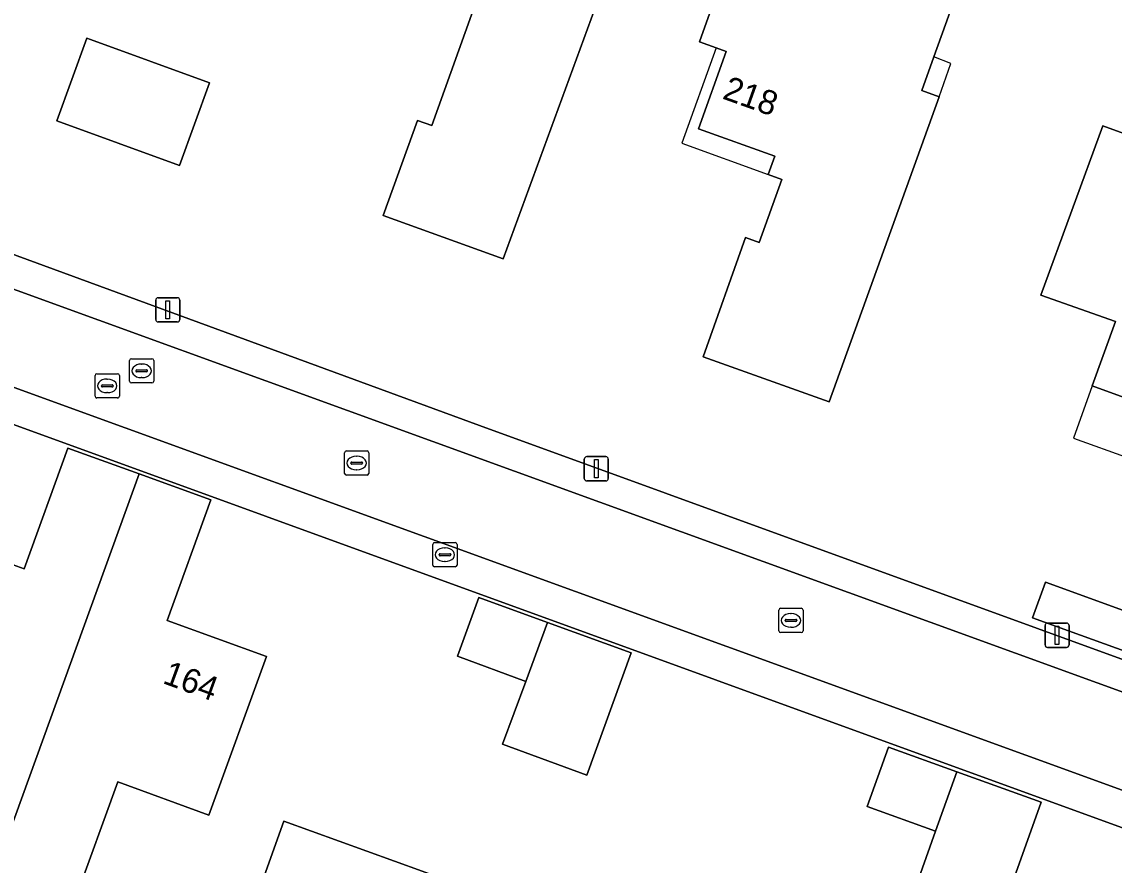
# Model space of a CAD drawing. Extents: x 155275 to 156265, y 382654 to 383635.
# Drawn here: x 155842.67 to 155887.75, y 382975.69 to 383010.47 of the extents above; entities that cross this region are included whole.
import ezdxf

# ---------------------------------------------------------------- set-up
doc = ezdxf.new("R2010")
doc.units = 0
for name, color, linetype in [('IMGEO_Brandkraan', 7, 'Continuous'), ('IMGEO_Erf', 7, 'Continuous'), ('IMGEO_Kolk', 7, 'Continuous'), ('IMGEO_Lichtmast', 7, 'Continuous'), ('IMGEO_Pand', 7, 'Continuous'), ('IMGEO_Pand_nummerreeks', 7, 'Continuous'), ('IMGEO_Pand_overbouw', 7, 'Continuous'), ('IMGEO_Rijbaan_lokaal_open', 7, 'Continuous'), ('IMGEO_Rioolput', 7, 'Continuous'), ('IMGEO_Voetpad_open', 7, 'Continuous')]:
    doc.layers.add(name, color=color, linetype=linetype)

msp = doc.modelspace()

# ---------------------------------------------------------------- linework, layer by layer
at = {"layer": 'IMGEO_Brandkraan'}
for p, q in [((155859.627, 382988.068), (155859.627, 382988.92)), ((155859.702, 382988.994), (155860.554, 382988.994)), ((155860.115, 382988.774), (155860.14, 382988.774)), ((155860.628, 382988.92), (155860.628, 382988.068)), ((155859.886, 382988.488), (155859.886, 382988.5)), ((155860.324, 382988.451), (155859.926, 382988.451)), ((155859.929, 382988.537), (155860.327, 382988.537)), ((155860.138, 382988.214), (155860.113, 382988.214)), ((155860.37, 382988.5), (155860.37, 382988.488)), ((155860.554, 382987.994), (155859.702, 382987.994))]:
    msp.add_line(p, q, dxfattribs=at)
for points in [[(155859.627, 382988.068), (155859.627, 382988.92)], [(155859.702, 382988.994), (155860.554, 382988.994)], [(155860.628, 382988.92), (155860.628, 382988.068)], [(155860.554, 382987.994), (155859.702, 382987.994)]]:
    msp.add_lwpolyline(points, dxfattribs=at)
for centre, radius, start, end in [((155859.704, 382988.918), 0.0765, 91.552, 178.448), ((155859.704, 382988.918), 0.0765, 91.552, 178.448), ((155860.552, 382988.918), 0.0765, 1.552, 88.448), ((155860.552, 382988.918), 0.0765, 1.552, 88.448), ((155859.926, 382988.497), 0.0403, 85.8775, 175.7526), ((155859.923, 382988.487), 0.0366, 178.938, 274.7102), ((155860.327, 382988.494), 0.043, 264.8664, 352.4533), ((155860.331, 382988.499), 0.0386, 1.7309, 96.639), ((155859.704, 382988.07), 0.0765, 181.552, 268.448), ((155859.704, 382988.07), 0.0765, 181.552, 268.448), ((155860.552, 382988.07), 0.0765, 271.552, 358.448), ((155860.552, 382988.07), 0.0765, 271.552, 358.448)]:
    msp.add_arc(centre, radius, start, end, dxfattribs=at)
for centre, major_axis, ratio, start_param, end_param in [((155860.114, 382988.494), (-0.387, 0.002), 0.722429, 4.712389, 7.853982), ((155860.139, 382988.494), (-0.39, 0.002), 0.717154, 1.570796, 4.712389)]:
    msp.add_ellipse(centre, major_axis=major_axis, ratio=ratio, start_param=start_param, end_param=end_param, dxfattribs=at)
at = {"layer": 'IMGEO_Erf'}
for points in [[(155874.118, 383022.07), (155815.634, 383043.488), (155805.118, 383014.525), (155861.561, 382993.83), (155892.261, 382982.665), (155902.833, 383011.607)], [(155861.487, 383011.501), (155860.894, 383011.717), (155856.676, 383013.255), (155859.79, 383021.938), (155866.043, 383019.627), (155865.514, 383018.043), (155867.383, 383017.419), (155866.395, 383014.46), (155867.37, 383014.134), (155866.468, 383011.433), (155862.536, 383000.703), (155857.581, 383002.491), (155858.991, 383006.402), (155859.584, 383006.197)], [(155871.739, 383009.255), (155871.329, 383009.401), (155870.641, 383009.646), (155873.267, 383017.02), (155882.058, 383013.885), (155880.313, 383009.036), (155879.812, 383007.643), (155880.526, 383007.379), (155875.99, 382994.801), (155870.783, 382996.663), (155872.541, 383001.578), (155873.106, 383001.376), (155874.035, 383003.975), (155873.47, 383004.177), (155873.743, 383004.94), (155870.598, 383006.064)], [(155850.407, 383007.954), (155849.167, 383004.553), (155844.112, 383006.396), (155845.352, 383009.797), (155845.493, 383009.746)], [(155887.289, 383006.185), (155889.215, 383005.483), (155889.922, 383007.421), (155891.006, 383007.026), (155891.151, 383006.973), (155892.124, 383009.662), (155898.589, 383007.324), (155897.186, 383003.474), (155897.411, 383003.391), (155897.936, 383003.196), (155896.655, 382999.777), (155896.075, 382999.984), (155895.342, 382998.021), (155897.361, 382997.282), (155892.159, 382983.084), (155884.378, 382985.893), (155884.916, 382987.368), (155888.598, 382986.024), (155890.664, 382991.645), (155891.448, 382993.777), (155886.85, 382995.454), (155887.812, 382998.113), (155884.727, 382999.207)], [(155815.563, 383003.587), (155803.373, 383007.958), (155803.344, 383007.878), (155814.627, 383003.794), (155812.383, 382997.713), (155807.505, 382999.513), (155802.482, 382985.7), (155800.143, 382986.554), (155799.514, 382984.832), (155798.857, 382983.032), (155794.84, 382984.507), (155794.244, 382982.888), (155817.258, 382974.414), (155845.91, 382964.137), (155880.792, 382951.626), (155889.819, 382976.447), (155889.87, 382976.588)], [(155840.019, 382981.509), (155837.391, 382982.474), (155838.538, 382985.6), (155837.416, 382986.01), (155838.657, 382989.39), (155842.761, 382987.916), (155844.568, 382992.891), (155847.501, 382991.829), (155850.461, 382990.758), (155848.665, 382985.778), (155852.768, 382984.295), (155850.381, 382977.751), (155846.624, 382979.121), (155844.881, 382974.314), (155848.641, 382972.949), (155846.046, 382965.802), (155838.99, 382968.361), (155831.934, 382970.92), (155832.069, 382971.267), (155834.531, 382978.054), (155838.252, 382976.693)], [(155863.462, 382983.266), (155860.642, 382984.304), (155861.532, 382986.731), (155864.36, 382985.703), (155867.817, 382984.447), (155865.992, 382979.402), (155862.509, 382980.678)], [(155878.437, 382980.551), (155881.26, 382979.539), (155884.744, 382978.29), (155882.935, 382973.245), (155879.452, 382974.493), (155880.383, 382977.091), (155877.559, 382978.104)], [(155853.474, 382977.5), (155859.184, 382975.435), (155860.453, 382974.972), (155867.583, 382972.373), (155865.394, 382966.345), (155864.103, 382966.792), (155861.667, 382960.114), (155855.679, 382962.284), (155856.389, 382964.171), (155850.842, 382966.173), (155852.91, 382971.892), (155851.641, 382972.351)]]:
    msp.add_lwpolyline(points, close=True, dxfattribs=at)
at = {"layer": 'IMGEO_Kolk'}
for p, q in [((155855.986, 382991.849), (155855.986, 382992.701)), ((155856.061, 382992.775), (155856.913, 382992.775)), ((155856.987, 382992.701), (155856.987, 382991.849)), ((155856.245, 382992.269), (155856.245, 382992.281)), ((155856.683, 382992.232), (155856.285, 382992.232)), ((155856.288, 382992.318), (155856.686, 382992.318)), ((155856.474, 382992.555), (155856.499, 382992.555)), ((155856.729, 382992.281), (155856.729, 382992.269)), ((155856.497, 382991.995), (155856.472, 382991.995)), ((155856.913, 382991.775), (155856.061, 382991.775)), ((155873.911, 382985.357), (155873.911, 382986.209)), ((155873.986, 382986.283), (155874.838, 382986.283)), ((155874.399, 382986.063), (155874.424, 382986.063)), ((155874.912, 382986.209), (155874.912, 382985.357)), ((155874.17, 382985.777), (155874.17, 382985.789)), ((155874.608, 382985.74), (155874.21, 382985.74)), ((155874.213, 382985.826), (155874.611, 382985.826)), ((155874.422, 382985.503), (155874.397, 382985.503)), ((155874.654, 382985.789), (155874.654, 382985.777)), ((155874.838, 382985.283), (155873.986, 382985.283))]:
    msp.add_line(p, q, dxfattribs=at)
for points in [[(155855.986, 382991.849), (155855.986, 382992.701)], [(155856.061, 382992.775), (155856.913, 382992.775)], [(155856.987, 382992.701), (155856.987, 382991.849)], [(155856.913, 382991.775), (155856.061, 382991.775)], [(155873.911, 382985.357), (155873.911, 382986.209)], [(155873.986, 382986.283), (155874.838, 382986.283)], [(155874.912, 382986.209), (155874.912, 382985.357)], [(155874.838, 382985.283), (155873.986, 382985.283)]]:
    msp.add_lwpolyline(points, dxfattribs=at)
for centre, radius, start, end in [((155856.063, 382992.699), 0.0765, 91.552, 178.448), ((155856.063, 382992.699), 0.0765, 91.552, 178.448), ((155856.911, 382992.699), 0.0765, 1.552, 88.448), ((155856.911, 382992.699), 0.0765, 1.552, 88.448), ((155856.285, 382992.278), 0.0403, 85.8775, 175.7526), ((155856.282, 382992.268), 0.0366, 178.938, 274.7102), ((155856.686, 382992.275), 0.043, 264.8664, 352.4533), ((155856.69, 382992.28), 0.0386, 1.7309, 96.639), ((155856.063, 382991.851), 0.0765, 181.552, 268.448), ((155856.063, 382991.851), 0.0765, 181.552, 268.448), ((155856.911, 382991.851), 0.0765, 271.552, 358.448), ((155856.911, 382991.851), 0.0765, 271.552, 358.448), ((155873.988, 382986.207), 0.0765, 91.552, 178.448), ((155873.988, 382986.207), 0.0765, 91.552, 178.448), ((155874.836, 382986.207), 0.0765, 1.552, 88.448), ((155874.836, 382986.207), 0.0765, 1.552, 88.448), ((155874.21, 382985.786), 0.0403, 85.8775, 175.7526), ((155874.207, 382985.776), 0.0366, 178.938, 274.7102), ((155874.611, 382985.783), 0.043, 264.8664, 352.4533), ((155874.615, 382985.788), 0.0386, 1.7309, 96.639), ((155873.988, 382985.359), 0.0765, 181.552, 268.448), ((155873.988, 382985.359), 0.0765, 181.552, 268.448), ((155874.836, 382985.359), 0.0765, 271.552, 358.448), ((155874.836, 382985.359), 0.0765, 271.552, 358.448)]:
    msp.add_arc(centre, radius, start, end, dxfattribs=at)
for centre, major_axis, ratio, start_param, end_param in [((155856.473, 382992.275), (-0.387, 0.002), 0.722429, 4.712389, 7.853982), ((155856.498, 382992.275), (-0.39, 0.002), 0.717154, 1.570796, 4.712389), ((155874.398, 382985.783), (-0.387, 0.002), 0.722429, 4.712389, 7.853982), ((155874.423, 382985.783), (-0.39, 0.002), 0.717154, 1.570796, 4.712389)]:
    msp.add_ellipse(centre, major_axis=major_axis, ratio=ratio, start_param=start_param, end_param=end_param, dxfattribs=at)
at = {"layer": 'IMGEO_Lichtmast'}
for p, q in [((155848.192, 382998.195), (155848.192, 382998.995)), ((155848.192, 382998.995), (155848.192, 382998.195)), ((155848.292, 382999.095), (155849.082, 382999.095)), ((155849.082, 382999.095), (155848.292, 382999.095)), ((155849.182, 382998.995), (155849.182, 382998.195)), ((155849.182, 382998.195), (155849.182, 382998.995)), ((155849.082, 382998.095), (155848.292, 382998.095)), ((155848.292, 382998.095), (155849.082, 382998.095)), ((155865.882, 382991.64), (155865.882, 382992.44)), ((155865.882, 382992.44), (155865.882, 382991.64)), ((155865.982, 382992.54), (155866.772, 382992.54)), ((155866.772, 382992.54), (155865.982, 382992.54)), ((155866.872, 382992.44), (155866.872, 382991.64)), ((155866.872, 382991.64), (155866.872, 382992.44)), ((155866.772, 382991.54), (155865.982, 382991.54)), ((155865.982, 382991.54), (155866.772, 382991.54)), ((155884.899, 382984.772), (155884.899, 382985.572)), ((155884.899, 382985.572), (155884.899, 382984.772)), ((155884.999, 382985.672), (155885.789, 382985.672)), ((155885.789, 382985.672), (155884.999, 382985.672)), ((155885.889, 382985.572), (155885.889, 382984.772)), ((155885.889, 382984.772), (155885.889, 382985.572)), ((155885.789, 382984.672), (155884.999, 382984.672)), ((155884.999, 382984.672), (155885.789, 382984.672))]:
    msp.add_line(p, q, dxfattribs=at)
for points in [[(155848.612, 382998.97), (155848.762, 382998.97), (155848.762, 382998.22), (155848.612, 382998.22), (155848.612, 382998.97)], [(155866.302, 382992.415), (155866.452, 382992.415), (155866.452, 382991.665), (155866.302, 382991.665), (155866.302, 382992.415)], [(155885.319, 382985.547), (155885.469, 382985.547), (155885.469, 382984.797), (155885.319, 382984.797), (155885.319, 382985.547)]]:
    msp.add_lwpolyline(points, dxfattribs=at)
for centre, start, end in [((155848.292, 382998.995), 90, 180), ((155848.292, 382998.995), 90, 180), ((155849.082, 382998.995), 0, 90), ((155849.082, 382998.995), 360, 90), ((155848.292, 382998.195), 180, 270), ((155848.292, 382998.195), 180, 270), ((155849.082, 382998.195), 270, 0), ((155849.082, 382998.195), 270, 0), ((155865.982, 382992.44), 90, 180), ((155865.982, 382992.44), 90, 180), ((155866.772, 382992.44), 0, 90), ((155866.772, 382992.44), 360, 90), ((155865.982, 382991.64), 180, 270), ((155865.982, 382991.64), 180, 270), ((155866.772, 382991.64), 270, 0), ((155866.772, 382991.64), 270, 0), ((155884.999, 382985.572), 90, 180), ((155884.999, 382985.572), 90, 180), ((155885.789, 382985.572), 0, 90), ((155885.789, 382985.572), 360, 90), ((155884.999, 382984.772), 180, 270), ((155884.999, 382984.772), 180, 270), ((155885.789, 382984.772), 270, 0), ((155885.789, 382984.772), 270, 0)]:
    msp.add_arc(centre, 0.1, start, end, dxfattribs=at)
at = {"layer": 'IMGEO_Pand'}
for points in [[(155866.468, 383011.433), (155867.37, 383014.134), (155866.395, 383014.46), (155867.383, 383017.419), (155865.514, 383018.043), (155866.043, 383019.627), (155859.79, 383021.938), (155856.676, 383013.255), (155860.894, 383011.717), (155861.487, 383011.501), (155859.584, 383006.197), (155858.991, 383006.402), (155857.581, 383002.491), (155862.536, 383000.703)], [(155880.526, 383007.379), (155879.812, 383007.643), (155880.313, 383009.036), (155882.058, 383013.885), (155873.267, 383017.02), (155870.641, 383009.646), (155871.329, 383009.401), (155871.739, 383009.255), (155870.598, 383006.064), (155873.743, 383004.94), (155873.47, 383004.177), (155874.035, 383003.975), (155873.106, 383001.376), (155872.541, 383001.578), (155870.783, 382996.663), (155875.99, 382994.801)], [(155850.407, 383007.954), (155845.493, 383009.746), (155845.352, 383009.797), (155844.112, 383006.396), (155849.167, 383004.553)], [(155897.361, 382997.282), (155895.342, 382998.021), (155896.075, 382999.984), (155896.655, 382999.777), (155897.936, 383003.196), (155897.411, 383003.391), (155897.186, 383003.474), (155898.589, 383007.324), (155892.124, 383009.662), (155891.151, 383006.973), (155891.006, 383007.026), (155889.922, 383007.421), (155889.215, 383005.483), (155887.289, 383006.185), (155884.727, 382999.207), (155887.812, 382998.113), (155886.85, 382995.454), (155891.448, 382993.777), (155890.664, 382991.645), (155888.598, 382986.024), (155884.916, 382987.368), (155884.378, 382985.893), (155892.159, 382983.084)], [(155847.501, 382991.829), (155844.568, 382992.891), (155842.761, 382987.916), (155838.657, 382989.39), (155837.416, 382986.01), (155838.538, 382985.6), (155837.391, 382982.474), (155840.019, 382981.509), (155838.252, 382976.693), (155834.531, 382978.054), (155832.069, 382971.267), (155831.934, 382970.92), (155838.99, 382968.361)], [(155847.501, 382991.829), (155838.99, 382968.361), (155846.046, 382965.802), (155848.641, 382972.949), (155844.881, 382974.314), (155846.624, 382979.121), (155850.381, 382977.751), (155852.768, 382984.295), (155848.665, 382985.778), (155850.461, 382990.758)], [(155864.36, 382985.703), (155861.532, 382986.731), (155860.642, 382984.304), (155863.462, 382983.266)], [(155864.36, 382985.703), (155863.462, 382983.266), (155862.509, 382980.678), (155865.992, 382979.402), (155867.817, 382984.447)], [(155881.26, 382979.539), (155878.437, 382980.551), (155877.559, 382978.104), (155880.383, 382977.091)], [(155884.744, 382978.29), (155881.26, 382979.539), (155880.383, 382977.091), (155879.452, 382974.493), (155882.935, 382973.245)], [(155860.453, 382974.972), (155859.184, 382975.435), (155853.474, 382977.5), (155851.641, 382972.351), (155852.91, 382971.892), (155850.842, 382966.173), (155856.389, 382964.171)]]:
    msp.add_lwpolyline(points, close=True, dxfattribs=at)
at = {"layer": 'IMGEO_Pand_overbouw'}
for points in [[(155871.329, 383009.401), (155869.903, 383005.467), (155873.47, 383004.177), (155873.743, 383004.94), (155870.598, 383006.064), (155871.739, 383009.255)], [(155880.313, 383009.036), (155879.812, 383007.643), (155880.526, 383007.379), (155881.018, 383008.75)], [(155886.85, 382995.454), (155886.073, 382993.306), (155890.664, 382991.645), (155891.448, 382993.777)]]:
    msp.add_lwpolyline(points, close=True, dxfattribs=at)
at = {"layer": 'IMGEO_Rijbaan_lokaal_open'}
msp.add_lwpolyline([(155804.618, 383013.141), (155802.336, 383013.969), (155798.601, 383015.34), (155797.305, 383011.771), (155800.988, 383010.419), (155803.857, 383009.375), (155815.828, 383005.02), (155890.354, 382977.962), (155892.703, 382977.109), (155896.479, 382975.739), (155897.78, 382979.312), (155894.626, 382980.459), (155893.94, 382980.709)], close=True, dxfattribs=at)
at = {"layer": 'IMGEO_Rioolput'}
for p, q in [((155847.11, 382995.653), (155847.11, 382996.505)), ((155847.185, 382996.579), (155848.037, 382996.579)), ((155847.598, 382996.359), (155847.623, 382996.359)), ((155848.111, 382996.505), (155848.111, 382995.653)), ((155845.689, 382995.033), (155845.689, 382995.885)), ((155845.764, 382995.959), (155846.616, 382995.959)), ((155846.69, 382995.885), (155846.69, 382995.033)), ((155847.369, 382996.073), (155847.369, 382996.085)), ((155847.807, 382996.036), (155847.409, 382996.036)), ((155847.412, 382996.122), (155847.81, 382996.122)), ((155847.853, 382996.085), (155847.853, 382996.073)), ((155845.948, 382995.453), (155845.948, 382995.465)), ((155846.386, 382995.416), (155845.988, 382995.416)), ((155845.991, 382995.502), (155846.389, 382995.502)), ((155846.177, 382995.739), (155846.202, 382995.739)), ((155846.432, 382995.465), (155846.432, 382995.453)), ((155848.037, 382995.579), (155847.185, 382995.579)), ((155847.621, 382995.799), (155847.596, 382995.799)), ((155846.616, 382994.959), (155845.764, 382994.959)), ((155846.2, 382995.179), (155846.175, 382995.179))]:
    msp.add_line(p, q, dxfattribs=at)
for points in [[(155847.11, 382995.653), (155847.11, 382996.505)], [(155847.185, 382996.579), (155848.037, 382996.579)], [(155848.111, 382996.505), (155848.111, 382995.653)], [(155845.689, 382995.033), (155845.689, 382995.885)], [(155845.764, 382995.959), (155846.616, 382995.959)], [(155846.69, 382995.885), (155846.69, 382995.033)], [(155848.037, 382995.579), (155847.185, 382995.579)], [(155846.616, 382994.959), (155845.764, 382994.959)]]:
    msp.add_lwpolyline(points, dxfattribs=at)
for centre, radius, start, end in [((155847.187, 382996.503), 0.0765, 91.552, 178.448), ((155847.187, 382996.503), 0.0765, 91.552, 178.448), ((155848.035, 382996.503), 0.0765, 1.552, 88.448), ((155848.035, 382996.503), 0.0765, 1.552, 88.448), ((155845.766, 382995.883), 0.0765, 91.552, 178.448), ((155845.766, 382995.883), 0.0765, 91.552, 178.448), ((155846.614, 382995.883), 0.0765, 1.552, 88.448), ((155846.614, 382995.883), 0.0765, 1.552, 88.448), ((155847.409, 382996.082), 0.0403, 85.8775, 175.7526), ((155847.406, 382996.072), 0.0366, 178.938, 274.7102), ((155847.81, 382996.079), 0.043, 264.8664, 352.4533), ((155847.814, 382996.084), 0.0386, 1.7309, 96.639), ((155845.988, 382995.462), 0.0403, 85.8775, 175.7526), ((155845.985, 382995.452), 0.0366, 178.938, 274.7102), ((155846.389, 382995.459), 0.043, 264.8664, 352.4533), ((155846.393, 382995.464), 0.0386, 1.7309, 96.639), ((155847.187, 382995.655), 0.0765, 181.552, 268.448), ((155847.187, 382995.655), 0.0765, 181.552, 268.448), ((155848.035, 382995.655), 0.0765, 271.552, 358.448), ((155848.035, 382995.655), 0.0765, 271.552, 358.448), ((155845.766, 382995.035), 0.0765, 181.552, 268.448), ((155845.766, 382995.035), 0.0765, 181.552, 268.448), ((155846.614, 382995.035), 0.0765, 271.552, 358.448), ((155846.614, 382995.035), 0.0765, 271.552, 358.448)]:
    msp.add_arc(centre, radius, start, end, dxfattribs=at)
for centre, major_axis, ratio, start_param, end_param in [((155847.597, 382996.079), (-0.387, 0.002), 0.722429, 4.712389, 7.853982), ((155847.622, 382996.079), (-0.39, 0.002), 0.717154, 1.570796, 4.712389), ((155846.176, 382995.459), (-0.387, 0.002), 0.722429, 4.712389, 7.853982), ((155846.201, 382995.459), (-0.39, 0.002), 0.717154, 1.570796, 4.712389)]:
    msp.add_ellipse(centre, major_axis=major_axis, ratio=ratio, start_param=start_param, end_param=end_param, dxfattribs=at)
at = {"layer": 'IMGEO_Voetpad_open'}
for points in [[(155805.118, 383014.525), (155804.618, 383013.141), (155893.94, 382980.709), (155894.626, 382980.459)], [(155894.687, 382981.843), (155893.451, 382982.278), (155892.261, 382982.665), (155861.561, 382993.83), (155805.118, 383014.525)]]:
    msp.add_lwpolyline(points, dxfattribs=at)
msp.add_lwpolyline([(155815.828, 383005.02), (155803.857, 383009.375), (155803.373, 383007.958), (155815.563, 383003.587), (155889.87, 382976.588), (155890.354, 382977.962)], close=True, dxfattribs=at)

# ---------------------------------------------------------------- texts
at = {"layer": 'IMGEO_Pand_nummerreeks'}
for s, rotation, p in [('218', 340.3335, (155871.541, 383007.32)), ('164', 339.9293, (155848.435, 382983.208))]:
    msp.add_text(s, height=1, rotation=rotation, dxfattribs=at).set_placement(p)

doc.saveas('drawing.dxf')
